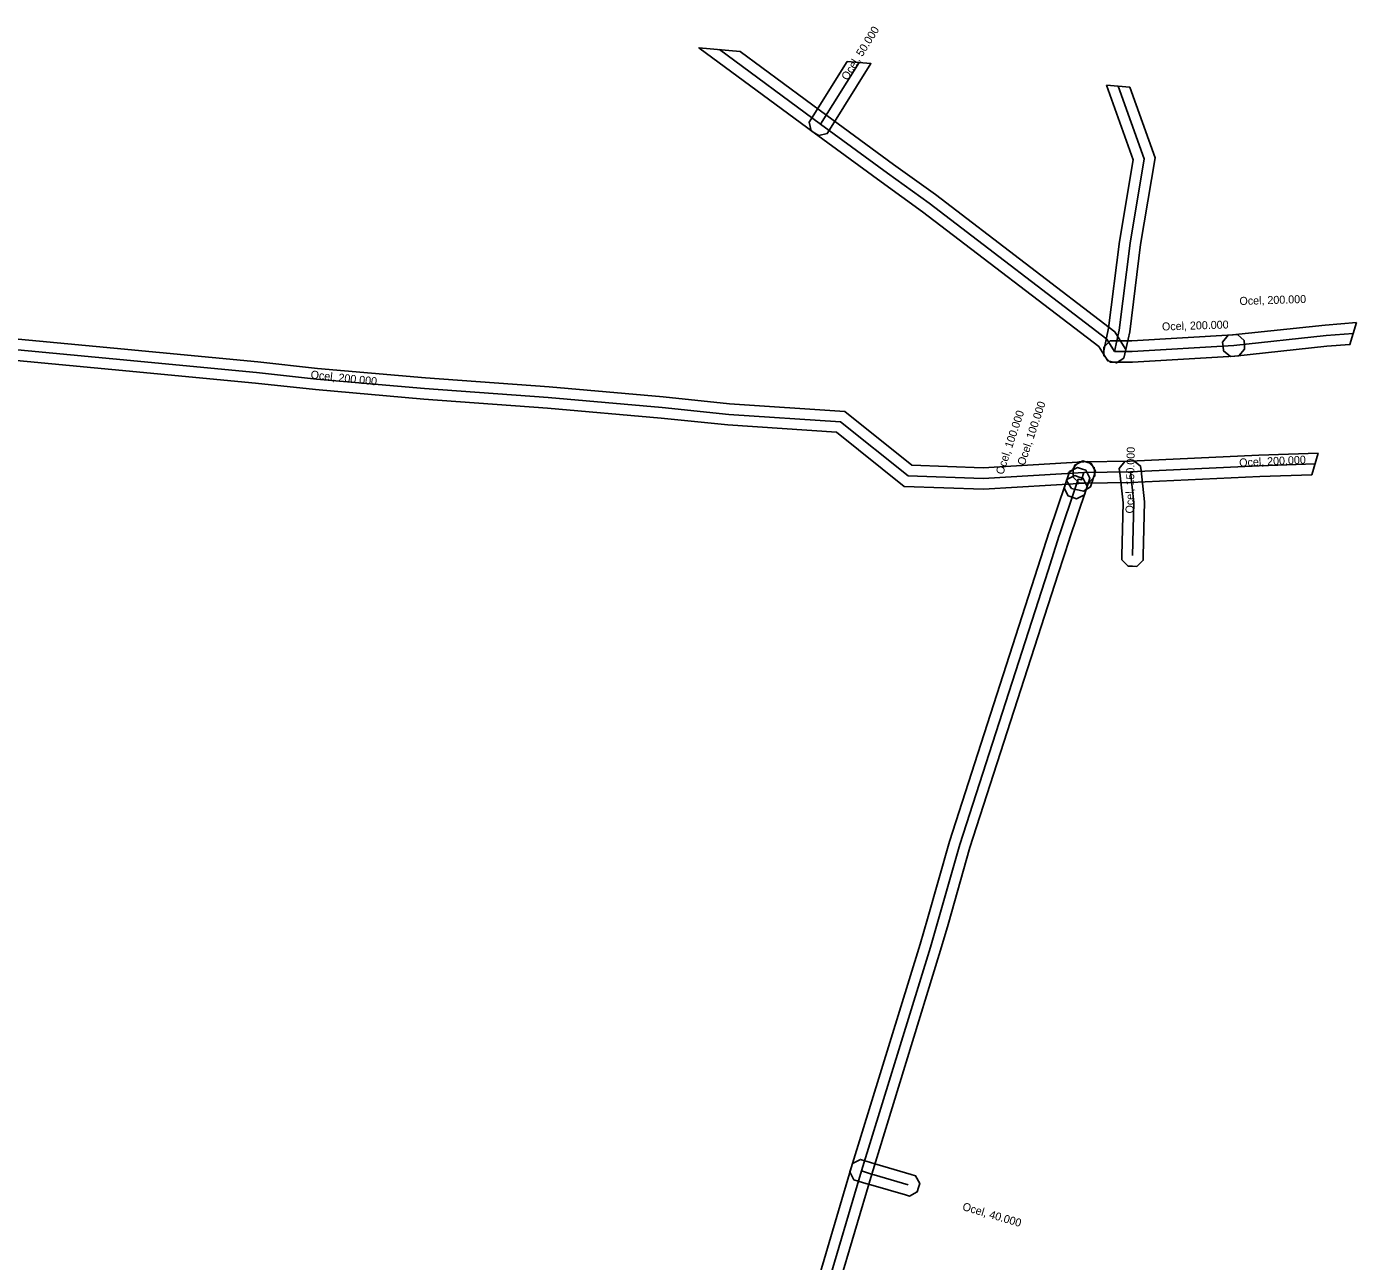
# Model space of a CAD drawing. Extents: x -888412 to -888163, y -1022526 to -1022295.
# Drawn here: x -888287.5 to -888162.9, y -1022410.3 to -1022294.7 of the extents above; entities that cross this region are included whole.
import ezdxf

# ---------------------------------------------------------------- set-up
doc = ezdxf.new("R2010")
doc.units = 0
for name, color, linetype in [('Vrstva 1', 7, 'Continuous'), ('Vrstva 14', 7, 'Continuous'), ('Vrstva 20', 7, 'Continuous')]:
    doc.layers.add(name, color=color, linetype=linetype)

msp = doc.modelspace()

# ---------------------------------------------------------------- linework, layer by layer
at = {"layer": 'Vrstva 1'}
for points in [[(-888213.742, -1022304.626), (-888224.543, -1022296.667), (-888220.692, -1022297.02), (-888212.558, -1022303.014), (-888206.302, -1022307.601), (-888202.394, -1022310.417), (-888185.59, -1022323.265), (-888184.764, -1022324.577), (-888184.543, -1022324.928), (-888184.727, -1022325.736), (-888185.077, -1022325.956), (-888185.428, -1022326.177), (-888186.236, -1022325.993), (-888186.456, -1022325.643), (-888187.09, -1022324.635), (-888203.586, -1022312.023), (-888207.478, -1022309.219)], [(-888210.66, -1022297.939), (-888208.431, -1022298.144), (-888212.302, -1022304.349), (-888212.521, -1022304.701), (-888213.328, -1022304.888), (-888213.679, -1022304.668), (-888214.031, -1022304.449), (-888214.218, -1022303.642), (-888213.998, -1022303.291)], [(-888186.374, -1022300.166), (-888184.177, -1022300.367), (-888181.801, -1022306.988), (-888183.16, -1022315.105), (-888184.183, -1022323.269), (-888184.633, -1022325.324), (-888184.722, -1022325.729), (-888185.419, -1022326.176), (-888185.824, -1022326.087), (-888186.229, -1022325.998), (-888186.676, -1022325.301), (-888186.587, -1022324.896), (-888186.157, -1022322.931), (-888185.14, -1022314.815), (-888183.859, -1022307.172)], [(-888162.943, -1022322.407), (-888163.545, -1022324.46), (-888165.699, -1022324.626), (-888174.335, -1022325.535), (-888174.747, -1022325.578), (-888175.392, -1022325.057), (-888175.435, -1022324.645), (-888175.478, -1022324.233), (-888174.957, -1022323.588), (-888174.545, -1022323.545), (-888165.881, -1022322.634)], [(-888173.418, -1022324.895), (-888173.968, -1022325.514), (-888174.381, -1022325.538), (-888183.931, -1022326.099), (-888185.603, -1022326.11), (-888186.017, -1022326.113), (-888186.607, -1022325.531), (-888186.61, -1022325.117), (-888186.613, -1022324.703), (-888186.031, -1022324.113), (-888185.617, -1022324.11), (-888183.997, -1022324.099), (-888174.499, -1022323.542), (-888174.085, -1022323.518), (-888173.466, -1022324.068), (-888173.442, -1022324.481)], [(-888166.529, -1022334.631), (-888167.121, -1022336.651), (-888172, -1022336.809), (-888184.089, -1022337.37), (-888188.464, -1022337.44), (-888188.878, -1022337.447), (-888189.473, -1022336.87), (-888189.48, -1022336.456), (-888189.487, -1022336.042), (-888188.91, -1022335.447), (-888188.496, -1022335.44), (-888184.151, -1022335.37), (-888172.078, -1022334.811)], [(-888189.975, -1022336.84), (-888189.884, -1022336.436), (-888189.439, -1022336.154), (-888189.437, -1022336.149), (-888189.316, -1022335.753), (-888188.585, -1022335.362), (-888188.189, -1022335.483), (-888187.793, -1022335.604), (-888187.402, -1022336.335), (-888187.523, -1022336.731), (-888187.733, -1022337.421), (-888187.848, -1022337.797), (-888188.527, -1022338.192), (-888188.91, -1022338.105), (-888189.22, -1022338.035), (-888189.624, -1022337.944), (-888190.067, -1022337.244)], [(-888183.815, -1022335.332), (-888183.17, -1022335.851), (-888183.126, -1022336.263), (-888182.809, -1022339.206), (-888182.91, -1022344.25), (-888182.918, -1022344.664), (-888183.516, -1022345.238), (-888183.93, -1022345.23), (-888184.344, -1022345.222), (-888184.918, -1022344.624), (-888184.91, -1022344.21), (-888184.811, -1022339.294), (-888185.114, -1022336.477), (-888185.158, -1022336.065), (-888184.639, -1022335.42), (-888184.227, -1022335.376)], [(-888188.294, -1022336.24), (-888187.921, -1022336.979), (-888188.05, -1022337.372), (-888188.3, -1022338.132), (-888188.43, -1022338.526), (-888189.169, -1022338.899), (-888189.562, -1022338.77), (-888189.956, -1022338.64), (-888190.329, -1022337.901), (-888190.2, -1022337.508), (-888189.95, -1022336.748), (-888189.82, -1022336.354), (-888189.081, -1022335.981), (-888188.688, -1022336.11)], [(-888210.147, -1022401.161), (-888209.411, -1022400.781), (-888209.016, -1022400.907), (-888208.557, -1022401.054), (-888207.982, -1022401.222), (-888207.854, -1022401.262), (-888204.652, -1022402.189), (-888204.254, -1022402.305), (-888203.854, -1022403.03), (-888203.969, -1022403.428), (-888204.085, -1022403.826), (-888204.81, -1022404.226), (-888205.208, -1022404.111), (-888208.426, -1022403.178), (-888208.558, -1022403.138), (-888209.143, -1022402.966), (-888209.624, -1022402.813), (-888210.019, -1022402.687), (-888210.399, -1022401.951), (-888210.273, -1022401.556)]]:
    msp.add_lwpolyline(points, close=True, dxfattribs=at)
for points in [[(-888288.979, -1022323.904), (-888279.386, -1022324.814), (-888265.889, -1022326.095), (-888260.293, -1022326.695), (-888250.17, -1022327.573), (-888238.59, -1022328.423), (-888227.905, -1022329.355), (-888221.675, -1022330.003), (-888210.89, -1022330.723), (-888204.584, -1022335.772), (-888197.919, -1022336.009), (-888188.54, -1022335.442), (-888188.127, -1022335.417), (-888187.507, -1022335.966), (-888187.482, -1022336.38), (-888187.457, -1022336.793), (-888188.006, -1022337.413), (-888188.42, -1022337.438), (-888197.895, -1022338.011), (-888205.316, -1022337.748), (-888211.65, -1022332.677), (-888221.845, -1022331.997), (-888228.095, -1022331.345), (-888238.75, -1022330.417), (-888250.33, -1022329.567), (-888260.487, -1022328.685), (-888266.091, -1022328.085), (-888279.574, -1022326.806), (-888289.161, -1022325.896)], [(-888216.64, -1022423.089), (-888210.277, -1022401.571), (-888203.818, -1022380.622), (-888203.131, -1022378.235), (-888201.067, -1022370.999), (-888192.782, -1022345.324), (-888191.721, -1022342.01), (-888191.697, -1022341.951), (-888190.198, -1022337.501), (-888190.065, -1022337.108), (-888189.323, -1022336.74), (-888188.931, -1022336.872), (-888188.538, -1022337.005), (-888188.17, -1022337.747), (-888188.302, -1022338.139), (-888189.821, -1022342.645), (-888189.839, -1022342.69), (-888190.878, -1022345.936), (-888199.153, -1022371.581), (-888201.209, -1022378.785), (-888201.902, -1022381.194), (-888208.363, -1022402.149), (-888214.72, -1022423.651)]]:
    msp.add_lwpolyline(points, dxfattribs=at)
at = {"layer": 'Vrstva 14'}
for p, q in [((-888222.618, -1022296.843), (-888213.15, -1022303.82)), ((-888213.15, -1022303.82), (-888209.546, -1022298.041)), ((-888189, -1022337.06), (-888189.25, -1022337.82)), ((-888188.48, -1022336.44), (-888184.12, -1022336.37)), ((-888189.25, -1022337.82), (-888190.759, -1022342.298)), ((-888202.86, -1022380.908), (-888209.32, -1022401.86)), ((-888209.32, -1022401.86), (-888215.68, -1022423.37))]:
    msp.add_line(p, q, dxfattribs=at)
for points in [[(-888185.61, -1022325.11), (-888185.17, -1022323.1), (-888184.15, -1022314.96), (-888182.83, -1022307.08), (-888185.276, -1022300.266)], [(-888213.15, -1022303.82), (-888206.89, -1022308.41), (-888202.99, -1022311.22), (-888186.34, -1022323.95), (-888185.61, -1022325.11)], [(-888188.48, -1022336.44), (-888197.907, -1022337.01), (-888204.95, -1022336.76), (-888211.27, -1022331.7), (-888221.76, -1022331), (-888228, -1022330.35), (-888238.67, -1022329.42), (-888250.25, -1022328.57), (-888260.39, -1022327.69), (-888265.99, -1022327.09), (-888279.48, -1022325.81), (-888289.07, -1022324.9), (-888302.26, -1022323.73), (-888312.84, -1022322.87), (-888324.29, -1022322.32), (-888335.13, -1022321.27)], [(-888174.44, -1022324.54), (-888165.79, -1022323.63), (-888163.244, -1022323.433)], [(-888174.44, -1022324.54), (-888183.964, -1022325.099), (-888185.61, -1022325.11)], [(-888184.12, -1022336.37), (-888172.039, -1022335.81), (-888166.825, -1022335.641)], [(-888189, -1022337.06), (-888188.69, -1022337.13), (-888188.48, -1022336.44)], [(-888184.12, -1022336.37), (-888183.81, -1022339.25), (-888183.91, -1022344.23)], [(-888190.759, -1022342.298), (-888190.78, -1022342.35), (-888191.83, -1022345.63), (-888200.11, -1022371.29), (-888202.17, -1022378.51), (-888202.86, -1022380.908)], [(-888209.32, -1022401.86), (-888208.85, -1022402.01), (-888208.27, -1022402.18), (-888208.14, -1022402.22), (-888204.93, -1022403.15)]]:
    msp.add_lwpolyline(points, dxfattribs=at)

# ---------------------------------------------------------------- texts
at = {"layer": 'Vrstva 20'}
for s, rotation, p in [('Ocel, 50.000', 58.04567, (-888210.63, -1022299.78)), ('Ocel, 200.000', 1.78299, (-888173.89, -1022320.76)), ('Ocel, 200.000', 1.78299, (-888181.15, -1022323.15)), ('Ocel, 200.000', 353.88448, (-888260.963, -1022327.629)), ('Ocel, 100.000', 71.37295, (-888196.05, -1022336.7)), ('Ocel, 100.000', 71.37295, (-888194.04, -1022335.85)), ('Ocel, 150.000', 88.84965, (-888183.831, -1022340.292)), ('Ocel, 200.000', 2.654, (-888173.908, -1022335.897)), ('Ocel, 40.000', 343.55273, (-888199.92, -1022405.51))]:
    msp.add_text(s, height=0.75, rotation=rotation, dxfattribs=at).set_placement(p)

doc.saveas('drawing.dxf')
